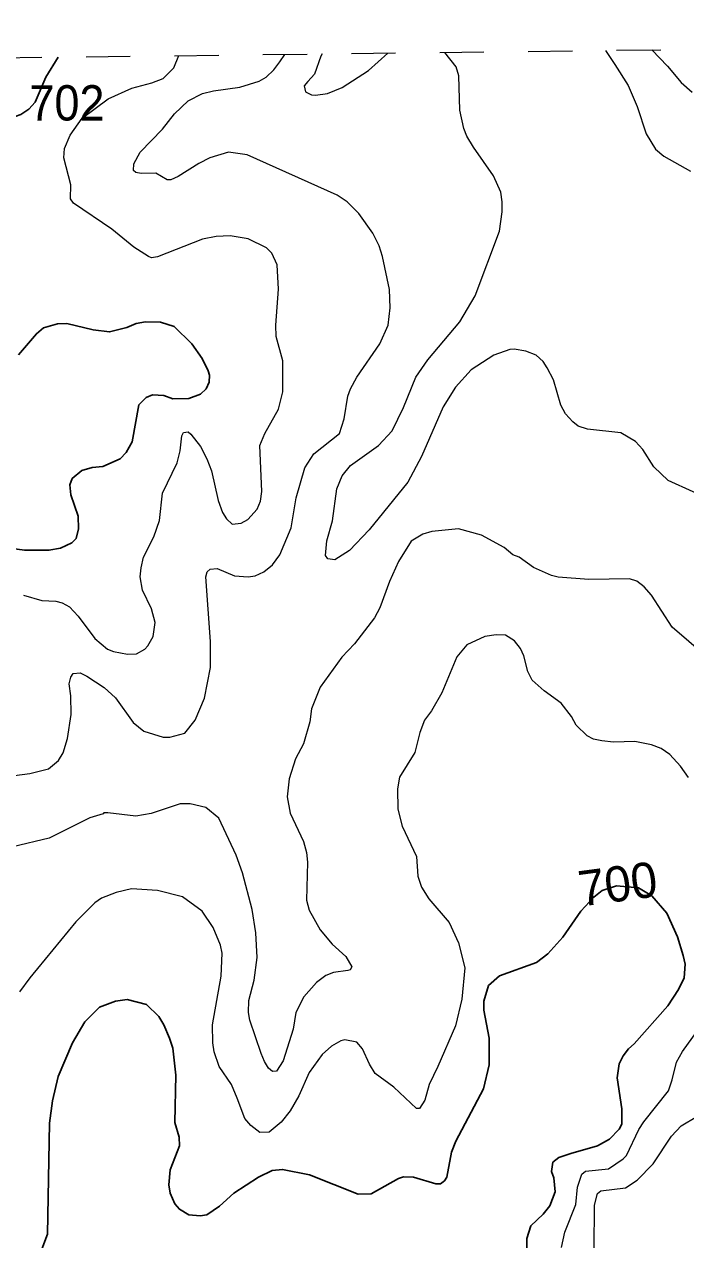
# Model space of a CAD drawing. Extents: x 294.2 to 320.3, y 7482.7 to 7510.7.
# Drawn here: x 313.761 to 315.257, y 7507.992 to 7510.744 of the extents above; entities that cross this region are included whole.
import ezdxf
from ezdxf.enums import TextEntityAlignment as Align

# ---------------------------------------------------------------- set-up
doc = ezdxf.new("R2010")
doc.units = 0
doc.header["$LTSCALE"] = 0.032
doc.linetypes.add('SHORT_DASHED', pattern=[2.7, 1.5, -1.2])
for name, color, linetype, lineweight in [('1', 7, 'Continuous', 25), ('2', 7, 'Continuous', 13), ('22', 7, 'SHORT_DASHED', 13)]:
    doc.layers.add(name, color=color, linetype=linetype, lineweight=lineweight)
doc.layers.add('61', color=7, linetype='Continuous')

msp = doc.modelspace()

# ---------------------------------------------------------------- linework, layer by layer
at = {"layer": '1'}
for points in [[(313.6408, 7510.6671), (313.6241, 7510.6348), (313.6219, 7510.6129), (313.6286, 7510.5699), (313.6407, 7510.548), (313.6574, 7510.5321), (313.6755, 7510.5238), (313.7012, 7510.5215), (313.7533, 7510.5397), (313.7719, 7510.5518), (313.7862, 7510.5676), (313.8102, 7510.6244), (313.8383, 7510.6695)], [(313.7116, 7509.5601), (313.762, 7509.5531), (313.8169, 7509.5531), (313.8433, 7509.5577), (313.8685, 7509.5698), (313.8785, 7509.58), (313.8839, 7509.6019), (313.8835, 7509.6305), (313.8663, 7509.6789), (313.8646, 7509.7015), (313.8696, 7509.7155), (313.8912, 7509.7338), (313.9145, 7509.7403), (313.9389, 7509.7429), (313.9783, 7509.7601), (313.9916, 7509.7746), (314.0055, 7509.7983), (314.0204, 7509.8822), (314.037, 7509.8989), (314.0515, 7509.9048), (314.077, 7509.9037), (314.0975, 7509.8962), (314.1335, 7509.8967), (314.1602, 7509.9064), (314.1724, 7509.9182), (314.1796, 7509.9333), (314.1802, 7509.9494), (314.1773, 7509.9593), (314.1639, 7509.9872), (314.1401, 7510.0206), (314.1006, 7510.0599), (314.0696, 7510.0695), (314.0352, 7510.0701), (314.0147, 7510.0663), (313.9936, 7510.0572), (313.9542, 7510.0475), (313.917, 7510.0523), (313.8577, 7510.0663), (313.8366, 7510.0658), (313.8045, 7510.0566), (313.7889, 7510.0432), (313.7485, 7509.9953)], [(315.0579, 7508.2047), (315.085, 7508.2203), (315.1066, 7508.2423), (315.1127, 7508.2542), (315.1127, 7508.2886), (315.1022, 7508.3585), (315.1066, 7508.3903), (315.1155, 7508.4086), (315.1277, 7508.4242), (315.141, 7508.4355), (315.217, 7508.522), (315.2414, 7508.5586), (315.2536, 7508.5855), (315.2563, 7508.6162), (315.2519, 7508.6355), (315.2391, 7508.678), (315.2147, 7508.7313), (315.1809, 7508.7705), (315.1504, 7508.7888), (315.1005, 7508.7931), (315.0683, 7508.7829), (315.0495, 7508.7678), (315.0201, 7508.7361), (314.9796, 7508.6775), (314.9452, 7508.6393), (314.9197, 7508.6199), (314.8364, 7508.5897), (314.8109, 7508.5677), (314.8004, 7508.5322), (314.801, 7508.5118), (314.8126, 7508.4483), (314.8126, 7508.3881), (314.7998, 7508.3337), (314.7371, 7508.2154), (314.7276, 7508.1902), (314.7171, 7508.1343), (314.7116, 7508.1257), (314.7027, 7508.1192), (314.6922, 7508.1187), (314.6417, 7508.1343), (314.619, 7508.1348), (314.6079, 7508.1311), (314.5457, 7508.0961), (314.5163, 7508.0956), (314.4065, 7508.1391), (314.3455, 7508.1515), (314.3222, 7508.1494), (314.2912, 7508.1343), (314.2352, 7508.0977), (314.2031, 7508.0686), (314.1742, 7508.0487), (314.1592, 7508.0463), (314.1337, 7508.0484), (314.1121, 7508.0614), (314.1015, 7508.0737), (314.091, 7508.0974), (314.0882, 7508.1168), (314.0916, 7508.1506), (314.1126, 7508.205), (314.1115, 7508.2243), (314.1015, 7508.2577), (314.1037, 7508.3647), (314.097, 7508.426), (314.0898, 7508.4486), (314.0771, 7508.4788), (314.0654, 7508.4976), (314.0377, 7508.5245), (313.9938, 7508.5358), (313.9678, 7508.5325), (313.9317, 7508.5191), (313.8984, 7508.4852), (313.8701, 7508.4384), (313.838, 7508.3621), (313.8252, 7508.3067), (313.8186, 7508.2561), (313.8136, 7508.0049), (313.8013, 7507.9709)], [(314.9619, 7508.1004), (314.9591, 7508.1327), (314.9541, 7508.1466), (314.9569, 7508.1676), (314.9701, 7508.1788), (314.9974, 7508.1875), (315.0579, 7508.2047)], [(314.8987, 7507.9004), (314.8981, 7507.995), (314.907, 7508.0241), (314.9353, 7508.0504), (314.9497, 7508.0692), (314.9619, 7508.1004)]]:
    msp.add_lwpolyline(points, dxfattribs=at)
at = {"layer": '2'}
for points in [[(314.3312, 7510.037), (314.33, 7510.0626), (314.3363, 7510.1443), (314.3331, 7510.1992), (314.321, 7510.226), (314.3089, 7510.2375), (314.268, 7510.2579), (314.2272, 7510.265), (314.1952, 7510.2637), (314.1646, 7510.2573), (314.0624, 7510.217), (314.049, 7510.2152), (314.042, 7510.2183), (314.0094, 7510.2394), (313.959, 7510.2803), (313.8728, 7510.339), (313.8658, 7510.3486), (313.8664, 7510.3805), (313.8511, 7510.4418), (313.8524, 7510.4622), (313.8651, 7510.4929), (313.8921, 7510.5313), (313.9513, 7510.5753), (314.0043, 7510.5988), (314.0497, 7510.611), (314.0752, 7510.6212), (314.0994, 7510.6449), (314.1107, 7510.6728)], [(314.5132, 7509.9451), (314.5655, 7510.0204), (314.5841, 7510.0626), (314.5892, 7510.1021), (314.5872, 7510.143), (314.5713, 7510.2184), (314.5643, 7510.2419), (314.5496, 7510.2707), (314.5177, 7510.3154), (314.4915, 7510.3422), (314.4691, 7510.3569), (314.2655, 7510.4482), (314.2233, 7510.4539), (314.1812, 7510.4418), (314.1563, 7510.4284), (314.1097, 7510.399), (314.0931, 7510.392), (314.0841, 7510.392), (314.0586, 7510.4067), (314.0254, 7510.406), (314.0139, 7510.408), (314.0082, 7510.4124), (314.0094, 7510.4278), (314.0235, 7510.4539), (314.0739, 7510.5063), (314.1014, 7510.5414), (314.132, 7510.5701), (314.1646, 7510.5867), (314.1889, 7510.5931), (314.2489, 7510.6014), (314.2929, 7510.6148), (314.3082, 7510.6238), (314.3254, 7510.641), (314.3392, 7510.6586), (314.3503, 7510.6757)], [(314.4352, 7510.6767), (314.4319, 7510.6714), (314.4176, 7510.6305), (314.4027, 7510.6142), (314.3944, 7510.6046), (314.3976, 7510.5906), (314.411, 7510.5842), (314.42, 7510.5835), (314.4468, 7510.5873), (314.48, 7510.6008), (314.54, 7510.6391), (314.5838, 7510.6785)], [(314.7622, 7510.4903), (314.7552, 7510.5082), (314.7468, 7510.5491), (314.7443, 7510.627), (314.7379, 7510.6474), (314.7124, 7510.6801)], [(315.0757, 7510.6845), (315.0967, 7510.6524), (315.1274, 7510.6053), (315.1478, 7510.558), (315.1682, 7510.4954), (315.1887, 7510.4609), (315.2079, 7510.445), (315.2685, 7510.4111)], [(315.1805, 7510.6858), (315.2162, 7510.6487), (315.2468, 7510.6123), (315.2717, 7510.5899)], [(314.8362, 7510.2758), (314.842, 7510.3192), (314.842, 7510.3422), (314.8395, 7510.3639), (314.8229, 7510.4009), (314.7775, 7510.4654), (314.7622, 7510.4903)], [(315.3311, 7509.6597), (315.2174, 7509.7107), (315.1855, 7509.742), (315.1606, 7509.781), (315.144, 7509.7995), (315.1108, 7509.8186), (315.0355, 7509.827), (315.0144, 7509.8339), (315.0022, 7509.8435), (314.9856, 7509.8621), (314.9748, 7509.8812), (314.9582, 7509.9387), (314.9442, 7509.9661), (314.9353, 7509.9805), (314.9192, 7509.9949), (314.8957, 7510.0038), (314.8695, 7510.0083), (314.8599, 7510.0076), (314.8232, 7509.9948), (314.7718, 7509.9617), (314.7366, 7509.9221), (314.7085, 7509.8774), (314.66, 7509.765), (314.6287, 7509.7075), (314.5413, 7509.599), (314.4966, 7509.5524), (314.464, 7509.5313), (314.448, 7509.5339), (314.4423, 7509.5416), (314.4455, 7509.5748), (314.4582, 7509.6195), (314.4685, 7509.6922), (314.48, 7509.7216), (314.4991, 7509.7446), (314.5624, 7509.7899), (314.5936, 7509.8238), (314.6191, 7509.8761), (314.6466, 7509.9451), (314.6741, 7509.984), (314.7462, 7510.0702), (314.7813, 7510.129), (314.8362, 7510.2758)], [(314.2986, 7509.6858), (314.2942, 7509.7906), (314.305, 7509.8174), (314.3363, 7509.8723), (314.3459, 7509.9119), (314.3459, 7509.9821), (314.3312, 7510.037)], [(314.3957, 7509.7395), (314.4161, 7509.7714), (314.4742, 7509.8173), (314.4845, 7509.8506), (314.4934, 7509.9017), (314.4991, 7509.9183), (314.5132, 7509.9451)], [(313.7598, 7509.4515), (313.8007, 7509.4394), (313.8326, 7509.4381), (313.8466, 7509.4343), (313.8632, 7509.4247), (313.883, 7509.4037), (313.9207, 7509.3532), (313.9494, 7509.3295), (313.9628, 7509.3238), (313.9948, 7509.3181), (314.0152, 7509.3187), (314.0337, 7509.3289), (314.0407, 7509.3366), (314.0529, 7509.3577), (314.0573, 7509.3896), (314.049, 7509.4203), (314.0286, 7509.4624), (314.0235, 7509.493), (314.0254, 7509.5135), (314.0311, 7509.5371), (314.0541, 7509.5837), (314.0669, 7509.6207), (314.0739, 7509.682), (314.1071, 7509.751), (314.1141, 7509.7778), (314.1173, 7509.8122), (314.1211, 7509.8199), (314.132, 7509.8212), (314.1378, 7509.8161), (314.1595, 7509.788), (314.1742, 7509.7599), (314.1844, 7509.7331), (314.1997, 7509.6654), (314.2099, 7509.6386), (314.2189, 7509.6246), (314.2316, 7509.6124), (314.2521, 7509.6143), (314.2667, 7509.6226), (314.2884, 7509.6463), (314.2955, 7509.6642), (314.2986, 7509.6858)], [(313.7394, 7509.0435), (313.7738, 7509.048), (313.816, 7509.0582), (313.839, 7509.0774), (313.8491, 7509.0946), (313.8594, 7509.1266), (313.867, 7509.1815), (313.8664, 7509.2236), (313.8626, 7509.2504), (313.8664, 7509.2657), (313.8721, 7509.274), (313.8875, 7509.2753), (313.9028, 7509.2683), (313.9418, 7509.2421), (313.9679, 7509.2191), (314.0075, 7509.1629), (314.0318, 7509.1438), (314.0752, 7509.1303), (314.0905, 7509.1303), (314.1244, 7509.1387), (314.148, 7509.1687), (314.1691, 7509.2185), (314.1824, 7509.2875), (314.1824, 7509.3462), (314.1722, 7509.493), (314.1748, 7509.5039), (314.1818, 7509.5103), (314.1978, 7509.5121), (314.2367, 7509.4949), (314.268, 7509.493), (314.2833, 7509.4955), (314.3031, 7509.5039), (314.3229, 7509.5198), (314.3395, 7509.5428), (314.365, 7509.6041), (314.3765, 7509.6718), (314.3957, 7509.7395)], [(315.3023, 7509.3143), (315.227, 7509.3787), (315.1797, 7509.4515), (315.1632, 7509.47), (315.1466, 7509.4828), (315.13, 7509.4886), (315.038, 7509.4866), (314.9691, 7509.4924), (314.9537, 7509.4962), (314.9128, 7509.5144), (314.8809, 7509.5377), (314.8663, 7509.5428), (314.8465, 7509.5594), (314.7954, 7509.5875), (314.7431, 7509.6015), (314.683, 7509.5952), (314.6626, 7509.5894), (314.6364, 7509.5734), (314.6077, 7509.5275), (314.5872, 7509.4821), (314.5655, 7509.4228), (314.5534, 7509.3998), (314.5081, 7509.3411), (314.4794, 7509.311), (314.4308, 7509.2428), (314.411, 7509.1942), (314.4072, 7509.1649), (314.3931, 7509.1151), (314.3746, 7509.0806), (314.3606, 7509.0359), (314.3561, 7508.995), (314.3625, 7508.958), (314.3925, 7508.8935), (314.3995, 7508.8686), (314.4021, 7508.8469), (314.3995, 7508.7613), (314.4053, 7508.7384), (314.4308, 7508.6937), (314.4576, 7508.6617), (314.4883, 7508.6336), (314.5023, 7508.61), (314.4985, 7508.6036), (314.4934, 7508.6017), (314.4608, 7508.5973), (314.443, 7508.5902), (314.4225, 7508.5743), (314.3933, 7508.5422), (314.3752, 7508.5066), (314.3695, 7508.4689), (314.3466, 7508.3974), (314.3319, 7508.3738), (314.3229, 7508.3731), (314.314, 7508.3808), (314.3044, 7508.3955), (314.2974, 7508.414), (314.2718, 7508.4894), (314.2687, 7508.5066), (314.2693, 7508.534), (314.2814, 7508.58), (314.2878, 7508.6311), (314.2853, 7508.6873), (314.2769, 7508.7396), (314.2546, 7508.8226), (314.2405, 7508.8629), (314.2016, 7508.9465), (314.1716, 7508.9707)], [(315.2634, 7509.0384), (315.2455, 7509.064), (315.2213, 7509.0908), (315.2018, 7509.1042), (315.1799, 7509.1126), (315.142, 7509.1203), (315.0938, 7509.1189), (315.0674, 7509.1217), (315.0484, 7509.1256), (315.0346, 7509.1328), (315.0099, 7509.1572), (314.9991, 7509.1764), (314.9754, 7509.207), (314.9371, 7509.2345), (314.9097, 7509.2587), (314.9001, 7509.2785), (314.8911, 7509.3143), (314.8835, 7509.3309), (314.8701, 7509.3481), (314.8496, 7509.3609), (314.8286, 7509.3615), (314.8031, 7509.3576), (314.7622, 7509.3392), (314.7398, 7509.3117), (314.7054, 7509.23), (314.6824, 7509.1897), (314.6664, 7509.1687), (314.6556, 7509.1406), (314.6447, 7509.0952), (314.6102, 7509.0397), (314.6051, 7509.0129), (314.6064, 7508.9669), (314.616, 7508.9286), (314.6485, 7508.8597), (314.6511, 7508.815), (314.66, 7508.7907), (314.676, 7508.7639), (314.722, 7508.7103), (314.7437, 7508.6643), (314.7577, 7508.6081), (314.7507, 7508.5366), (314.7366, 7508.4766), (314.697, 7508.3846), (314.6773, 7508.3438), (314.6671, 7508.308), (314.6549, 7508.2895), (314.6486, 7508.2895), (314.5974, 7508.338), (314.5553, 7508.3686), (314.5419, 7508.3897), (314.5266, 7508.4248), (314.5132, 7508.4395)], [(313.9413, 7508.9588), (313.9399, 7508.9561), (313.9092, 7508.9471), (313.8173, 7508.9012), (313.7355, 7508.882)], [(314.1716, 7508.9707), (314.1365, 7508.9791), (314.1135, 7508.9791), (314.0484, 7508.9574), (314.0136, 7508.951), (313.9505, 7508.9588), (313.9413, 7508.9588)], [(314.3823, 7508.3182), (314.3625, 7508.2844), (314.342, 7508.2582), (314.3153, 7508.2359), (314.2942, 7508.2352), (314.2738, 7508.2512), (314.2604, 7508.2671), (314.2431, 7508.3131), (314.2297, 7508.3438), (314.2023, 7508.3846), (314.1908, 7508.4178), (314.1875, 7508.4383), (314.1869, 7508.4791), (314.2064, 7508.5892), (314.2092, 7508.6413), (314.2054, 7508.6592), (314.1888, 7508.6988), (314.164, 7508.736), (314.1192, 7508.7683), (314.0624, 7508.783), (314.0037, 7508.7868), (313.9693, 7508.7787), (313.936, 7508.7653), (313.9211, 7508.7553), (313.8779, 7508.7122), (313.7738, 7508.5851), (313.7508, 7508.5532)], [(314.9761, 7507.9747), (314.9837, 7508.0092), (315.0088, 7508.0723), (315.0129, 7508.1113), (315.0221, 7508.1406), (315.0307, 7508.1473), (315.0829, 7508.1528), (315.1162, 7508.1751), (315.1231, 7508.1829), (315.1512, 7508.2416), (315.1627, 7508.2594), (315.2184, 7508.3293), (315.227, 7508.3544), (315.2367, 7508.3942), (315.2499, 7508.4181), (315.3228, 7508.5187)], [(314.5132, 7508.4395), (314.4864, 7508.4446), (314.4775, 7508.4427), (314.4563, 7508.4306), (314.4353, 7508.4114), (314.4053, 7508.3706), (314.3823, 7508.3182)], [(315.0502, 7507.9709), (315.0514, 7508.0705), (315.0578, 7508.0973), (315.0654, 7508.1031), (315.1215, 7508.1096), (315.1474, 7508.1269), (315.1836, 7508.1643), (315.2251, 7508.2269), (315.2468, 7508.2499), (315.3177, 7508.2921)]]:
    msp.add_lwpolyline(points, dxfattribs=at)
at = {"layer": '22'}
msp.add_lwpolyline([(294.2515, 7510.4214), (307.9016, 7510.5978), (319.9762, 7510.7437)], dxfattribs=at)

# ---------------------------------------------------------------- texts
at = {"layer": '61', "width": 0.95}
msp.add_text('702', height=0.08, dxfattribs=at).set_placement((313.8578, 7510.5259), align=Align.CENTER)
at = {"layer": '61'}
msp.add_text('700', height=0.08, rotation=7.591, dxfattribs=at).set_placement((315.1088, 7508.7583), align=Align.CENTER)

doc.saveas('drawing.dxf')
